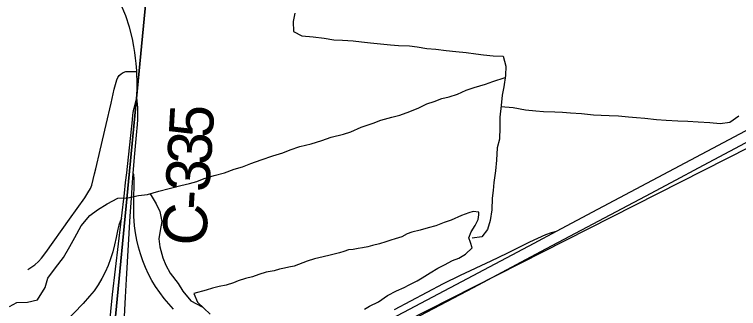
# Model space of a CAD drawing. Extents: x 0 to 1134, y 0 to 440.
# Drawn here: x 837.333 to 838.269, y 359.173 to 359.553 of the extents above; entities that cross this region are included whole.
import ezdxf

# ---------------------------------------------------------------- set-up
doc = ezdxf.new("R2010")
doc.units = 0
for name, color, linetype in [('GM_X_County_Road', 7, 'Continuous'), ('GM_X_County_Road_Text', 7, 'Continuous'), ('GM_X_Interchange_Ramps', 7, 'Continuous'), ('GM_X_Interstate_Route', 7, 'Continuous'), ('GM_X_Minor_Lake', 7, 'Continuous'), ('GM_X_Minor_River', 7, 'Continuous'), ('GM_X_Rail_Line', 7, 'Continuous'), ('GM_X_Section', 7, 'Continuous'), ('GM_X_State_Route', 7, 'Continuous')]:
    doc.layers.add(name, color=color, linetype=linetype)

msp = doc.modelspace()

# ---------------------------------------------------------------- linework, layer by layer
at = {"layer": 'GM_X_County_Road'}
msp.add_line((837.4864, 359.34779), (837.48857, 359.37351), dxfattribs=at)
for points in [[(837.49088, 359.47957), (837.49085, 359.4804), (837.49055, 359.48491), (837.49013, 359.48971), (837.48932, 359.49656), (837.48845, 359.5039), (837.4872, 359.51168), (837.48522, 359.52193), (837.48156, 359.53693), (837.47672, 359.5516), (837.46959, 359.56872), (837.46565, 359.57663), (837.46263, 359.58252), (837.45911, 359.58886), (837.45469, 359.59577), (837.45118, 359.60096), (837.4459, 359.60833), (837.44159, 359.6139), (837.43449, 359.62266), (837.42838, 359.62988), (837.41781, 359.64254), (837.39213, 359.67345), (837.39159, 359.67411)], [(837.35011, 359.22307), (837.35907, 359.22937), (837.36368, 359.23334), (837.36776, 359.23786), (837.37334, 359.24523), (837.40379, 359.28835), (837.42365, 359.31613), (837.42761, 359.32233), (837.43113, 359.32792), (837.43267, 359.33234), (837.43463, 359.33964), (837.43628, 359.3471), (837.43797, 359.35362), (837.4436, 359.37783), (837.45136, 359.41107), (837.45762, 359.4383), (837.46185, 359.45645), (837.46419, 359.46554), (837.46521, 359.46856), (837.46654, 359.4715), (837.46832, 359.47422), (837.47063, 359.47656), (837.47342, 359.47829), (837.47657, 359.47926), (837.47984, 359.47959), (837.48297, 359.47959), (837.49088, 359.47957)], [(837.49078, 359.44568), (837.49125, 359.46015), (837.49125, 359.46687), (837.49105, 359.47579), (837.49088, 359.47957)], [(837.44634, 359.00204), (837.44671, 359.01003), (837.44923, 359.06357), (837.44998, 359.07744), (837.451, 359.09118), (837.45213, 359.10908), (837.45377, 359.129), (837.4553, 359.14692), (837.45955, 359.19095), (837.47116, 359.28935), (837.47501, 359.32203), (837.47651, 359.33575), (837.47792, 359.34846), (837.48524, 359.41672), (837.48601, 359.42351), (837.48628, 359.42579), (837.48686, 359.4288), (837.48763, 359.43217), (837.48847, 359.43553), (837.49078, 359.44568)], [(837.48857, 359.37351), (837.49057, 359.39724), (837.4917, 359.41101), (837.49208, 359.41727), (837.49237, 359.42343), (837.49237, 359.42676), (837.49213, 359.4325), (837.49078, 359.44568)], [(837.47752, 359.21073), (837.48238, 359.29236), (837.48391, 359.31555), (837.4854, 359.33599), (837.4864, 359.34779)], [(837.46839, 359.03132), (837.46984, 359.0628), (837.47614, 359.18756), (837.47752, 359.21073)]]:
    msp.add_lwpolyline(points, dxfattribs=at)
at = {"layer": 'GM_X_Interchange_Ramps'}
for points in [[(837.53857, 359.17179), (837.53221, 359.17864), (837.5262, 359.1858), (837.52055, 359.19325), (837.51532, 359.201), (837.51052, 359.20902), (837.50613, 359.21728), (837.50218, 359.22575), (837.49866, 359.23441), (837.4956, 359.24324), (837.49303, 359.25223), (837.49094, 359.26134), (837.48932, 359.27054), (837.48813, 359.27982), (837.48723, 359.29224), (837.48699, 359.30656), (837.48732, 359.34166), (837.48731, 359.34386), (837.48696, 359.3461), (837.4864, 359.34779)], [(837.47116, 359.28935), (837.46925, 359.28535), (837.46766, 359.28072), (837.46636, 359.27541), (837.46421, 359.26478), (837.4622, 359.255), (837.45987, 359.24595), (837.45709, 359.23704), (837.45384, 359.22828), (837.45012, 359.21972), (837.4459, 359.21139), (837.44111, 359.20338), (837.43576, 359.19574), (837.4299, 359.18847), (837.42156, 359.17922), (837.39772, 359.15463), (837.28325, 359.03582)]]:
    msp.add_lwpolyline(points, dxfattribs=at)
at = {"layer": 'GM_X_Interstate_Route'}
for points in [[(838.18791, 359.33925), (838.21685, 359.3548), (838.31839, 359.40869), (838.44733, 359.47721), (838.50497, 359.50775), (838.58723, 359.55157), (838.6613, 359.59091), (838.80117, 359.66537), (838.89977, 359.71812), (838.92442, 359.73133), (838.94906, 359.74454), (838.96647, 359.75378), (838.99022, 359.76639), (839.06993, 359.80838), (839.18797, 359.87091), (839.26464, 359.912), (839.33609, 359.94968), (839.41001, 359.98933), (839.5265, 360.05106)], [(837.33081, 358.97925), (837.35857, 358.98307), (837.38623, 358.98762), (837.41377, 358.99291), (837.44116, 358.9989), (837.44624, 359.00016), (837.46719, 359.00532), (837.46837, 359.00561), (837.48942, 359.01127), (837.51331, 359.01826), (837.53407, 359.02487), (837.5576, 359.03303), (837.58383, 359.04283), (837.60983, 359.05325), (837.63273, 359.063), (837.65539, 359.07334), (837.67775, 359.08427), (837.71089, 359.10143), (837.79044, 359.14374), (837.91117, 359.20783), (838.00446, 359.25735), (838.03352, 359.27278), (838.08677, 359.30107), (838.36926, 359.45135)], [(838.02047, 359.25031), (838.14844, 359.31804), (838.18791, 359.33925)], [(837.82388, 359.17151), (837.88719, 359.20485), (837.90943, 359.21601), (837.94881, 359.23458), (837.96951, 359.2444), (837.99914, 359.25893), (838.0195, 359.26837), (838.02688, 359.27087), (838.03352, 359.27278)], [(837.84001, 359.15444), (837.92616, 359.20009), (838.00017, 359.23956), (838.02047, 359.25031)]]:
    msp.add_lwpolyline(points, dxfattribs=at)
at = {"layer": 'GM_X_Minor_Lake'}
for points in [[(837.93284, 359.29404), (837.93315, 359.29755), (837.9256, 359.2984), (837.91991, 359.29658), (837.91042, 359.2929), (837.89711, 359.287), (837.88801, 359.28408), (837.87737, 359.27967), (837.86751, 359.27714), (837.85727, 359.27423), (837.84627, 359.27133), (837.84058, 359.26951), (837.83335, 359.26543), (837.825, 359.26288), (837.81931, 359.26105), (837.81286, 359.25886), (837.80451, 359.2563), (837.79579, 359.25414), (837.78934, 359.25232), (837.78253, 359.25127), (837.77685, 359.2502), (837.77078, 359.24914), (837.76473, 359.24845), (837.75866, 359.24663), (837.75297, 359.24481), (837.74083, 359.24192), (837.73173, 359.23938), (837.72074, 359.23686), (837.71125, 359.23395), (837.70556, 359.23174), (837.69416, 359.22734), (837.68735, 359.22628), (837.68166, 359.22484), (837.67559, 359.2234), (837.66839, 359.22159), (837.65816, 359.21982), (837.64867, 359.21652), (837.64032, 359.21359), (837.63123, 359.21143), (837.62174, 359.20852), (837.61604, 359.20593), (837.60655, 359.20302), (837.59746, 359.20123), (837.58874, 359.19907), (837.58039, 359.19651), (837.56463, 359.19204)], [(837.78533, 359.17204), (837.7918, 359.17575), (837.80321, 359.1813), (837.81503, 359.18949), (837.82644, 359.19541), (837.83632, 359.19984), (837.84279, 359.20317), (837.85343, 359.20835), (837.85991, 359.21243), (837.87019, 359.21875), (837.88009, 359.22469), (837.88846, 359.22914), (837.89911, 359.23469), (837.90709, 359.238), (837.91585, 359.2432), (837.92426, 359.25106), (837.92246, 359.25828), (837.91989, 359.26399), (837.92301, 359.27191), (837.9284, 359.28018), (837.93227, 359.28771), (837.93284, 359.29404)], [(837.56463, 359.19204), (837.56924, 359.18074), (837.58568, 359.16538)]]:
    msp.add_lwpolyline(points, dxfattribs=at)
at = {"layer": 'GM_X_Minor_River'}
for points in [[(837.69519, 359.55507), (837.69316, 359.54411), (837.69338, 359.53122), (837.70428, 359.52579), (837.719, 359.52447), (837.73296, 359.5224), (837.74541, 359.52036), (837.75674, 359.51984), (837.77072, 359.51929), (837.78129, 359.51803), (837.79299, 359.51675), (837.81866, 359.51416), (837.82922, 359.5129), (837.84359, 359.51272), (837.8534, 359.51147), (837.86584, 359.50904), (837.87755, 359.50852), (837.89075, 359.50646), (837.90321, 359.50518), (837.9168, 359.50387), (837.92925, 359.50221), (837.93907, 359.50095), (837.95152, 359.49966), (837.96437, 359.49913), (837.96799, 359.4862), (837.96747, 359.47446), (837.96539, 359.45971), (837.96299, 359.44875), (837.96169, 359.4355), (837.95999, 359.42037), (837.96021, 359.40711), (837.95964, 359.39196), (837.95686, 359.38062), (837.9559, 359.36472), (837.9546, 359.3511), (837.95252, 359.33559), (837.95164, 359.32537), (837.95038, 359.31553), (837.94982, 359.30038), (837.94775, 359.28639), (837.94421, 359.27506), (837.93691, 359.2653), (837.92442, 359.26356)], [(837.32651, 359.17536), (837.33603, 359.18054), (837.34964, 359.18076), (837.36253, 359.18401), (837.37255, 359.1998), (837.3761, 359.21188), (837.38572, 359.22541), (837.39609, 359.23854), (837.4042, 359.25284), (837.41077, 359.26451), (837.41889, 359.27957), (837.4304, 359.29307), (837.44032, 359.30052), (837.45251, 359.30833), (837.46658, 359.31536), (837.47944, 359.31596), (837.49308, 359.31883), (837.50482, 359.3202), (837.51961, 359.32457), (837.53288, 359.32819), (837.54805, 359.3318), (837.55904, 359.33469), (837.56852, 359.33723), (837.57802, 359.3409), (837.59092, 359.34492), (837.60419, 359.34816), (837.61672, 359.35294), (837.62734, 359.35622), (837.63835, 359.36025), (837.65164, 359.36501), (837.66682, 359.37013), (837.67972, 359.37415), (837.68922, 359.3782), (837.70175, 359.38222), (837.71615, 359.38583), (837.73019, 359.3902), (837.74234, 359.3946), (837.75826, 359.3982), (837.76775, 359.40149), (837.78105, 359.40739), (837.79623, 359.41251), (837.80649, 359.41655), (837.82052, 359.42017), (837.83076, 359.42308), (837.84367, 359.42785), (837.85544, 359.43225), (837.86571, 359.43743), (837.8752, 359.44073), (837.88507, 359.4444), (837.89455, 359.44655), (837.90556, 359.45021), (837.91658, 359.45538), (837.9272, 359.45866), (837.94162, 359.46303), (837.95112, 359.4667), (837.96709, 359.47177)], [(837.96156, 359.4343), (837.97754, 359.43304), (837.99337, 359.42981), (838.00658, 359.42852), (838.01678, 359.42763), (838.03113, 359.42708), (838.04134, 359.42696), (838.05153, 359.42607), (838.06588, 359.42514), (838.08136, 359.42344), (838.09118, 359.42294), (838.10138, 359.42243), (838.11347, 359.42191), (838.12668, 359.42061), (838.13687, 359.41973), (838.14745, 359.41884), (838.16255, 359.41752), (838.17501, 359.41661), (838.19012, 359.41567), (838.20334, 359.41513), (838.21656, 359.41421), (838.23167, 359.41327), (838.24488, 359.41197), (838.25737, 359.41372), (838.26919, 359.42191)], [(837.5082, 359.3212), (837.51601, 359.30832), (837.5208, 359.29841), (837.52329, 359.28549), (837.52125, 359.27377), (837.5196, 359.2628), (837.52061, 359.25256), (837.52459, 359.23811), (837.52863, 359.22859), (837.53417, 359.21829), (837.54421, 359.20491), (837.55052, 359.19498), (837.56095, 359.18273), (837.57537, 359.17501)]]:
    msp.add_lwpolyline(points, dxfattribs=at)
at = {"layer": 'GM_X_Rail_Line'}
msp.add_lwpolyline([(837.45186, 358.95937), (838.5805, 359.53288), (839.88447, 360.22108), (840.05937, 360.30888), (840.40723, 360.49599), (840.56702, 360.60273), (840.72293, 360.70777)], dxfattribs=at)
at = {"layer": 'GM_X_Section'}
for points in [[(836.48425, 359.84459), (837.44124, 359.74248), (837.51839, 359.73596), (837.4241, 358.7547), (836.38861, 358.85213)], [(837.51839, 359.73596), (838.46587, 359.64288), (838.38225, 358.66569), (837.4241, 358.7547)]]:
    msp.add_lwpolyline(points, close=True, dxfattribs=at)
at = {"layer": 'GM_X_State_Route'}
for points in [[(838.18791, 359.33925), (838.21685, 359.3548), (838.31839, 359.40869), (838.44733, 359.47721), (838.50497, 359.50775), (838.58723, 359.55157), (838.6613, 359.59091), (838.80117, 359.66537), (838.89977, 359.71812), (838.92442, 359.73133), (838.94906, 359.74454), (838.96647, 359.75378), (838.99022, 359.76639), (839.06993, 359.80838), (839.18797, 359.87091), (839.26464, 359.912), (839.33609, 359.94968), (839.41001, 359.98933), (839.5265, 360.05106)], [(838.02047, 359.25031), (838.14844, 359.31804), (838.18791, 359.33925)], [(837.84001, 359.15444), (837.92616, 359.20009), (838.00017, 359.23956), (838.02047, 359.25031)]]:
    msp.add_lwpolyline(points, dxfattribs=at)

# ---------------------------------------------------------------- texts
at = {"layer": 'GM_X_County_Road_Text'}
for s, rotation, p in [('5', 86.66574, (837.58881, 359.3927)), ('3', 86.48522, (837.58665, 359.35757)), ('3', 86.44602, (837.58447, 359.3226)), ('-', 86.44067, (837.58302, 359.2993)), ('C', 86.43035, (837.58012, 359.25271))]:
    msp.add_text(s, height=0.05682, rotation=rotation, dxfattribs=at).set_placement(p)

doc.saveas('drawing.dxf')
